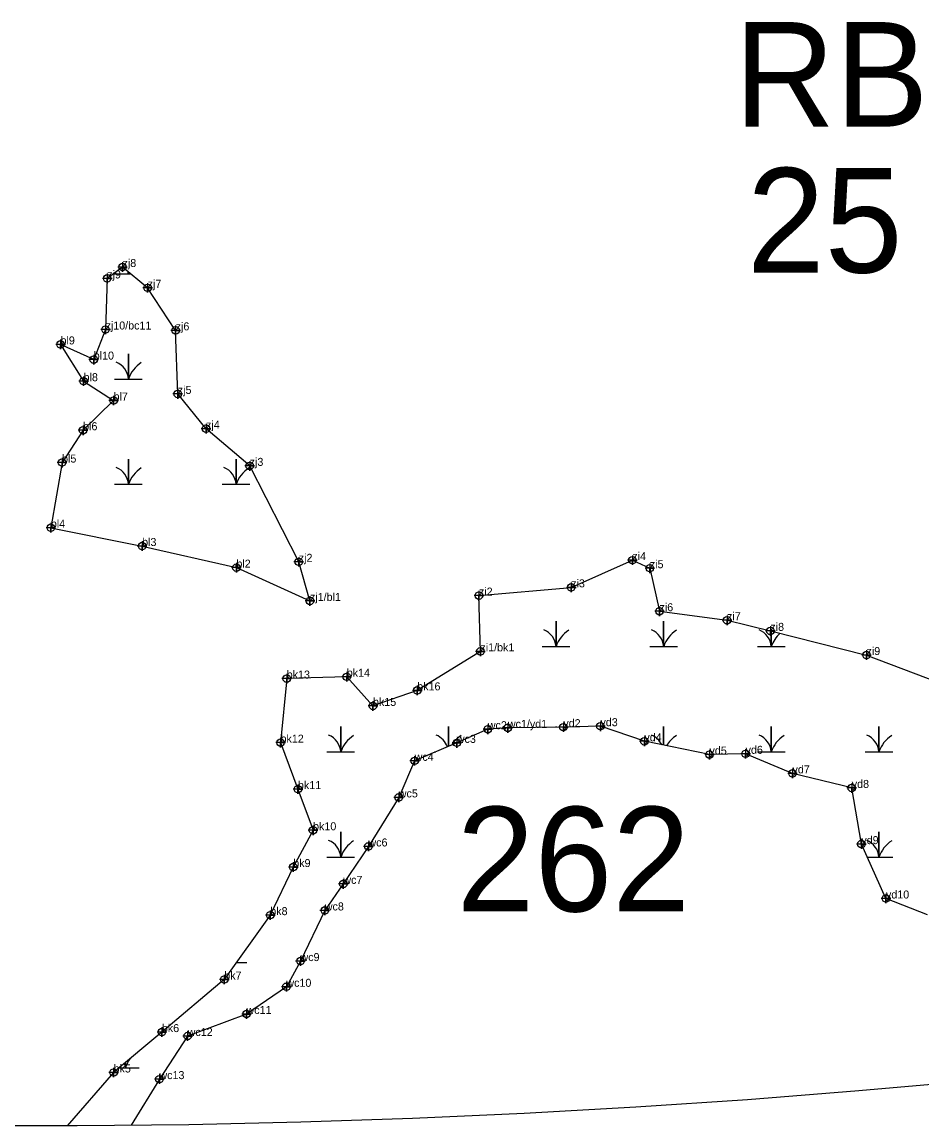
# Model space of a CAD drawing. Extents: x 2071991 to 2268989, y 436479 to 469629.
# Drawn here: x 2222499 to 2223061, y 436786 to 437475 of the extents above; entities that cross this region are included whole.
import ezdxf

# ---------------------------------------------------------------- set-up
doc = ezdxf.new("R2010")
doc.units = 0
for name, color, linetype in [('approx_PSA', 7, 'Continuous'), ('Default', 7, 'Continuous'), ('Exist Environmental Wetland Boundary', 7, 'Continuous'), ('Exist Environmental Wetland Boundary Cogo Comment', 7, 'Continuous'), ('Exist Environmental Wetland Boundary Cogo Point CELL', 7, 'Continuous'), ('Exist Hydro Swamp or Marsh', 7, 'Continuous')]:
    doc.layers.add(name, color=color, linetype=linetype)

msp = doc.modelspace()

# ---------------------------------------------------------------- linework, layer by layer
at = {"layer": 'approx_PSA'}
for p, q in [((2223091.14, 436813.8), (2223021.62, 436807.56)), ((2223021.62, 436807.56), (2222952.03, 436802.1)), ((2222952.03, 436802.1), (2222882.38, 436797.42)), ((2222812.68, 436793.52), (2222742.94, 436790.4)), ((2222882.38, 436797.42), (2222812.68, 436793.52)), ((2222603.39, 436786.5), (2222533.58, 436785.73)), ((2222673.17, 436788.06), (2222603.39, 436786.5)), ((2222742.94, 436790.4), (2222673.17, 436788.06)), ((2222533.58, 436785.73), (2222463.78, 436785.73))]:
    msp.add_line(p, q, dxfattribs=at)
at = {"layer": 'Exist Environmental Wetland Boundary'}
msp.add_lwpolyline([(2222678.94, 437113.66), (2222671.95, 437138.1), (2222641.29, 437198.03), (2222614.08, 437221.25), (2222596.41, 437242.97), (2222595.08, 437282.68), (2222577.59, 437309.25), (2222561.9, 437322.26), (2222552.35, 437315.12), (2222551.3, 437283.22), (2222543.94, 437264.43), (2222523.21, 437273.91), (2222537.6, 437250.93), (2222556.32, 437238.86), (2222537.3, 437220.3), (2222524.17, 437200.12), (2222517.16, 437159.39), (2222574.15, 437147.97), (2222633.01, 437134.45)], close=True, dxfattribs=at)
for points in [[(2222785.35, 437082.17), (2222784.41, 437117), (2222842.02, 437122.15), (2222880.21, 437139.14), (2222891.1, 437134.11), (2222897.14, 437107.23), (2222939.31, 437101.62), (2222966.35, 437094.96), (2223026.38, 437079.88), (2223078.67, 437060.04)], [(2222785.35, 437082.17), (2222745.89, 437057.79), (2222718.28, 437048.09), (2222701.91, 437066.28), (2222664.42, 437065.17), (2222660.56, 437025.14), (2222671.42, 436996.1), (2222680.87, 436970.41), (2222668.5, 436947.42), (2222654.15, 436917.39), (2222625.42, 436877.18), (2222586.46, 436844.34), (2222556.31, 436819.11), (2222527.37, 436785.73)], [(2223064.49, 436917.5), (2223038.53, 436927.79), (2223023.17, 436961.76), (2223017.18, 436996.86), (2222980.19, 437005.96), (2222950.9, 437018.17), (2222928.35, 437017.71), (2222887.69, 437025.99), (2222860.28, 437035.41), (2222837.11, 437034.81), (2222802.47, 437034.35), (2222789.96, 437033.53), (2222770.61, 437025), (2222744.29, 437013.79), (2222734.38, 436990.93), (2222715.43, 436960.31), (2222699.76, 436936.91), (2222688.19, 436920.33), (2222673, 436888.7), (2222664.19, 436872.65), (2222639.31, 436855.63), (2222602.57, 436841.89), (2222584.94, 436814.96), (2222567.3, 436786.1)]]:
    msp.add_lwpolyline(points, dxfattribs=at)
at = {"layer": 'Exist Environmental Wetland Boundary Cogo Point CELL'}
for points in [[(2222561.9, 437325.26), (2222561.9, 437319.26), (2222561.9, 437322.26), (2222564.9, 437322.26), (2222558.9, 437322.26)], [(2222552.35, 437318.12), (2222552.35, 437312.12), (2222552.35, 437315.12), (2222555.35, 437315.12), (2222549.35, 437315.12)], [(2222577.59, 437312.25), (2222577.59, 437306.25), (2222577.59, 437309.25), (2222580.59, 437309.25), (2222574.59, 437309.25)], [(2222551.3, 437286.22), (2222551.3, 437280.22), (2222551.3, 437283.22), (2222554.3, 437283.22), (2222548.3, 437283.22)], [(2222595.08, 437285.68), (2222595.08, 437279.68), (2222595.08, 437282.68), (2222598.08, 437282.68), (2222592.08, 437282.68)], [(2222523.21, 437276.91), (2222523.21, 437270.91), (2222523.21, 437273.91), (2222526.21, 437273.91), (2222520.21, 437273.91)], [(2222543.94, 437267.43), (2222543.94, 437261.43), (2222543.94, 437264.43), (2222546.94, 437264.43), (2222540.94, 437264.43)], [(2222537.6, 437253.93), (2222537.6, 437247.93), (2222537.6, 437250.93), (2222540.6, 437250.93), (2222534.6, 437250.93)], [(2222556.32, 437241.86), (2222556.32, 437235.86), (2222556.32, 437238.86), (2222559.32, 437238.86), (2222553.32, 437238.86)], [(2222596.41, 437245.97), (2222596.41, 437239.97), (2222596.41, 437242.97), (2222599.41, 437242.97), (2222593.41, 437242.97)], [(2222537.3, 437223.3), (2222537.3, 437217.3), (2222537.3, 437220.3), (2222540.3, 437220.3), (2222534.3, 437220.3)], [(2222614.08, 437224.25), (2222614.08, 437218.25), (2222614.08, 437221.25), (2222617.08, 437221.25), (2222611.08, 437221.25)], [(2222524.17, 437203.12), (2222524.17, 437197.12), (2222524.17, 437200.12), (2222527.17, 437200.12), (2222521.17, 437200.12)], [(2222641.29, 437201.03), (2222641.29, 437195.03), (2222641.29, 437198.03), (2222644.29, 437198.03), (2222638.29, 437198.03)], [(2222517.16, 437162.39), (2222517.16, 437156.39), (2222517.16, 437159.39), (2222520.16, 437159.39), (2222514.16, 437159.39)], [(2222574.15, 437150.97), (2222574.15, 437144.97), (2222574.15, 437147.97), (2222577.15, 437147.97), (2222571.15, 437147.97)], [(2222671.95, 437141.1), (2222671.95, 437135.1), (2222671.95, 437138.1), (2222674.95, 437138.1), (2222668.95, 437138.1)], [(2222880.21, 437142.14), (2222880.21, 437136.14), (2222880.21, 437139.14), (2222883.21, 437139.14), (2222877.21, 437139.14)], [(2222633.01, 437137.45), (2222633.01, 437131.45), (2222633.01, 437134.45), (2222636.01, 437134.45), (2222630.01, 437134.45)], [(2222891.1, 437137.11), (2222891.1, 437131.11), (2222891.1, 437134.11), (2222894.1, 437134.11), (2222888.1, 437134.11)], [(2222842.02, 437125.15), (2222842.02, 437119.15), (2222842.02, 437122.15), (2222845.02, 437122.15), (2222839.02, 437122.15)], [(2222784.41, 437120), (2222784.41, 437114), (2222784.41, 437117), (2222787.41, 437117), (2222781.41, 437117)], [(2222678.94, 437116.66), (2222678.94, 437110.66), (2222678.94, 437113.66), (2222681.94, 437113.66), (2222675.94, 437113.66)], [(2222897.14, 437110.23), (2222897.14, 437104.23), (2222897.14, 437107.23), (2222900.14, 437107.23), (2222894.14, 437107.23)], [(2222939.31, 437104.62), (2222939.31, 437098.62), (2222939.31, 437101.62), (2222942.31, 437101.62), (2222936.31, 437101.62)], [(2222966.35, 437097.96), (2222966.35, 437091.96), (2222966.35, 437094.96), (2222969.35, 437094.96), (2222963.35, 437094.96)], [(2222785.35, 437085.17), (2222785.35, 437079.17), (2222785.35, 437082.17), (2222788.35, 437082.17), (2222782.35, 437082.17)], [(2223026.38, 437082.88), (2223026.38, 437076.88), (2223026.38, 437079.88), (2223029.38, 437079.88), (2223023.38, 437079.88)], [(2222701.91, 437069.28), (2222701.91, 437063.28), (2222701.91, 437066.28), (2222704.91, 437066.28), (2222698.91, 437066.28)], [(2222664.42, 437068.17), (2222664.42, 437062.17), (2222664.42, 437065.17), (2222667.42, 437065.17), (2222661.42, 437065.17)], [(2222745.89, 437060.79), (2222745.89, 437054.79), (2222745.89, 437057.79), (2222748.89, 437057.79), (2222742.89, 437057.79)], [(2222718.28, 437051.09), (2222718.28, 437045.09), (2222718.28, 437048.09), (2222721.28, 437048.09), (2222715.28, 437048.09)], [(2222789.96, 437036.53), (2222789.96, 437030.53), (2222789.96, 437033.53), (2222792.96, 437033.53), (2222786.96, 437033.53)], [(2222802.47, 437037.35), (2222802.47, 437031.35), (2222802.47, 437034.35), (2222805.47, 437034.35), (2222799.47, 437034.35)], [(2222837.11, 437037.81), (2222837.11, 437031.81), (2222837.11, 437034.81), (2222840.11, 437034.81), (2222834.11, 437034.81)], [(2222860.28, 437038.41), (2222860.28, 437032.41), (2222860.28, 437035.41), (2222863.28, 437035.41), (2222857.28, 437035.41)], [(2222660.56, 437028.14), (2222660.56, 437022.14), (2222660.56, 437025.14), (2222663.56, 437025.14), (2222657.56, 437025.14)], [(2222770.61, 437028), (2222770.61, 437022), (2222770.61, 437025), (2222773.61, 437025), (2222767.61, 437025)], [(2222887.69, 437028.99), (2222887.69, 437022.99), (2222887.69, 437025.99), (2222890.69, 437025.99), (2222884.69, 437025.99)], [(2222928.35, 437020.71), (2222928.35, 437014.71), (2222928.35, 437017.71), (2222931.35, 437017.71), (2222925.35, 437017.71)], [(2222950.9, 437021.17), (2222950.9, 437015.17), (2222950.9, 437018.17), (2222953.9, 437018.17), (2222947.9, 437018.17)], [(2222744.29, 437016.79), (2222744.29, 437010.79), (2222744.29, 437013.79), (2222747.29, 437013.79), (2222741.29, 437013.79)], [(2222980.19, 437008.96), (2222980.19, 437002.96), (2222980.19, 437005.96), (2222983.19, 437005.96), (2222977.19, 437005.96)], [(2223017.18, 436999.86), (2223017.18, 436993.86), (2223017.18, 436996.86), (2223020.18, 436996.86), (2223014.18, 436996.86)], [(2222671.42, 436999.1), (2222671.42, 436993.1), (2222671.42, 436996.1), (2222674.42, 436996.1), (2222668.42, 436996.1)], [(2222734.38, 436993.93), (2222734.38, 436987.93), (2222734.38, 436990.93), (2222737.38, 436990.93), (2222731.38, 436990.93)], [(2222680.87, 436973.41), (2222680.87, 436967.41), (2222680.87, 436970.41), (2222683.87, 436970.41), (2222677.87, 436970.41)], [(2222715.43, 436963.31), (2222715.43, 436957.31), (2222715.43, 436960.31), (2222718.43, 436960.31), (2222712.43, 436960.31)], [(2223023.17, 436964.76), (2223023.17, 436958.76), (2223023.17, 436961.76), (2223026.17, 436961.76), (2223020.17, 436961.76)], [(2222668.5, 436950.42), (2222668.5, 436944.42), (2222668.5, 436947.42), (2222671.5, 436947.42), (2222665.5, 436947.42)], [(2222699.76, 436939.91), (2222699.76, 436933.91), (2222699.76, 436936.91), (2222702.76, 436936.91), (2222696.76, 436936.91)], [(2223038.53, 436930.79), (2223038.53, 436924.79), (2223038.53, 436927.79), (2223041.53, 436927.79), (2223035.53, 436927.79)], [(2222654.15, 436920.39), (2222654.15, 436914.39), (2222654.15, 436917.39), (2222657.15, 436917.39), (2222651.15, 436917.39)], [(2222688.19, 436923.33), (2222688.19, 436917.33), (2222688.19, 436920.33), (2222691.19, 436920.33), (2222685.19, 436920.33)], [(2222673, 436891.7), (2222673, 436885.7), (2222673, 436888.7), (2222676, 436888.7), (2222670, 436888.7)], [(2222625.42, 436880.18), (2222625.42, 436874.18), (2222625.42, 436877.18), (2222628.42, 436877.18), (2222622.42, 436877.18)], [(2222664.19, 436875.65), (2222664.19, 436869.65), (2222664.19, 436872.65), (2222667.19, 436872.65), (2222661.19, 436872.65)], [(2222639.31, 436858.63), (2222639.31, 436852.63), (2222639.31, 436855.63), (2222642.31, 436855.63), (2222636.31, 436855.63)], [(2222586.46, 436847.34), (2222586.46, 436841.34), (2222586.46, 436844.34), (2222589.46, 436844.34), (2222583.46, 436844.34)], [(2222602.57, 436844.89), (2222602.57, 436838.89), (2222602.57, 436841.89), (2222605.57, 436841.89), (2222599.57, 436841.89)], [(2222556.31, 436822.11), (2222556.31, 436816.11), (2222556.31, 436819.11), (2222559.31, 436819.11), (2222553.31, 436819.11)], [(2222584.94, 436817.96), (2222584.94, 436811.96), (2222584.94, 436814.96), (2222587.94, 436814.96), (2222581.94, 436814.96)]]:
    msp.add_lwpolyline(points, dxfattribs=at)
for centre in [(2222561.9, 437322.26), (2222552.35, 437315.12), (2222577.59, 437309.25), (2222551.3, 437283.22), (2222595.08, 437282.68), (2222523.21, 437273.91), (2222543.94, 437264.43), (2222537.6, 437250.93), (2222556.32, 437238.86), (2222596.41, 437242.97), (2222537.3, 437220.3), (2222614.08, 437221.25), (2222524.17, 437200.12), (2222641.29, 437198.03), (2222517.16, 437159.39), (2222574.15, 437147.97), (2222671.95, 437138.1), (2222880.21, 437139.14), (2222633.01, 437134.45), (2222891.1, 437134.11), (2222842.02, 437122.15), (2222784.41, 437117), (2222678.94, 437113.66), (2222897.14, 437107.23), (2222939.31, 437101.62), (2222966.35, 437094.96), (2222785.35, 437082.17), (2223026.38, 437079.88), (2222701.91, 437066.28), (2222664.42, 437065.17), (2222745.89, 437057.79), (2222718.28, 437048.09), (2222789.96, 437033.53), (2222802.47, 437034.35), (2222837.11, 437034.81), (2222860.28, 437035.41), (2222660.56, 437025.14), (2222770.61, 437025), (2222887.69, 437025.99), (2222950.9, 437018.17), (2222744.29, 437013.79), (2222928.35, 437017.71), (2222980.19, 437005.96), (2222671.42, 436996.1), (2222734.38, 436990.93), (2223017.18, 436996.86), (2222680.87, 436970.41), (2222715.43, 436960.31), (2223023.17, 436961.76), (2222668.5, 436947.42), (2222699.76, 436936.91), (2223038.53, 436927.79), (2222654.15, 436917.39), (2222688.19, 436920.33), (2222673, 436888.7), (2222625.42, 436877.18), (2222664.19, 436872.65), (2222639.31, 436855.63), (2222586.46, 436844.34), (2222602.57, 436841.89), (2222556.31, 436819.11), (2222584.94, 436814.96)]:
    msp.add_circle(centre, 2.34, dxfattribs=at)
at = {"layer": 'Exist Hydro Swamp or Marsh'}
for p, q in [((2222756.74, 437019.4), (2222757.45, 437019.4)), ((2222633.03, 436887.83), (2222639.53, 436887.83))]:
    msp.add_line(p, q, dxfattribs=at)
for points in [[(2222556.99, 437318.08), (2222565.59, 437318.08), (2222565.59, 437319.2)], [(2222565.59, 437319.2), (2222565.59, 437318.08), (2222566.95, 437318.08)], [(2222556.99, 437252.29), (2222565.59, 437252.29), (2222565.59, 437268.08), (2222565.59, 437252.29), (2222574.19, 437252.29)], [(2222556.99, 437186.51), (2222565.59, 437186.51), (2222565.59, 437202.29), (2222565.59, 437186.51), (2222574.19, 437186.51)], [(2222624.19, 437186.51), (2222632.79, 437186.51), (2222632.79, 437202.29), (2222632.79, 437186.51), (2222641.4, 437186.51)], [(2222632.79, 437134.49), (2222632.79, 437136.51), (2222632.79, 437134.49)], [(2222823.94, 437085.18), (2222832.54, 437085.18), (2222832.54, 437100.96), (2222832.54, 437085.18), (2222841.14, 437085.18)], [(2222891.14, 437085.18), (2222899.74, 437085.18), (2222899.74, 437100.96), (2222899.74, 437085.18), (2222908.35, 437085.18)], [(2222958.35, 437085.18), (2222966.95, 437085.18), (2222966.95, 437094.81)], [(2222966.95, 437094.81), (2222966.95, 437085.18), (2222975.55, 437085.18)], [(2222689.53, 437019.4), (2222698.13, 437019.4), (2222698.13, 437035.18), (2222698.13, 437019.4), (2222706.74, 437019.4)], [(2222765.34, 437022.76), (2222765.34, 437035.18), (2222765.34, 437022.76)], [(2222832.54, 437034.75), (2222832.54, 437035.18), (2222832.54, 437034.75)], [(2222899.74, 437023.53), (2222899.74, 437035.18), (2222899.74, 437023.53)], [(2222958.35, 437019.4), (2222966.95, 437019.4), (2222966.95, 437035.18), (2222966.95, 437019.4), (2222975.55, 437019.4)], [(2223025.55, 437019.4), (2223034.15, 437019.4), (2223034.15, 437035.18), (2223034.15, 437019.4), (2223042.75, 437019.4)], [(2222689.53, 436953.62), (2222698.13, 436953.62), (2222698.13, 436969.4), (2222698.13, 436953.62), (2222706.74, 436953.62)], [(2223026.85, 436953.62), (2223034.15, 436953.62), (2223034.15, 436969.4), (2223034.15, 436953.62), (2223042.75, 436953.62)], [(2222559.83, 436822.05), (2222563.73, 436822.05), (2222563.73, 436825.32)], [(2222563.73, 436825.32), (2222563.73, 436822.05), (2222572.33, 436822.05)]]:
    msp.add_lwpolyline(points, dxfattribs=at)
for centre, radius, start, end in [((2222553.32, 437317.19), 12.3, 4.14034, 10.03464), ((2222583.83, 437312.01), 19.22, 158.87528, 161.62219), ((2222553.32, 437251.41), 12.3, 4.14034, 67.53497), ((2222583.83, 437246.23), 19.22, 122.12745, 161.62219), ((2222553.32, 437185.63), 12.3, 4.14034, 67.53497), ((2222583.83, 437180.45), 19.22, 122.12745, 161.62219), ((2222620.53, 437185.63), 12.3, 4.14034, 67.53497), ((2222651.04, 437180.45), 19.22, 122.12745, 161.62219), ((2222651.04, 437114.67), 19.22, 122.12745, 122.25053), ((2222820.27, 437084.29), 12.3, 4.14034, 67.53497), ((2222850.78, 437079.12), 19.22, 122.12745, 161.62219), ((2222887.48, 437084.29), 12.3, 4.14034, 67.53497), ((2222917.99, 437079.12), 19.22, 122.12745, 161.62219), ((2222954.68, 437084.29), 12.3, 4.14034, 67.53497), ((2222985.19, 437079.12), 19.22, 131.78708, 161.62219), ((2222685.87, 437018.51), 12.3, 4.14034, 67.53497), ((2222716.38, 437013.34), 19.22, 122.12745, 161.62219), ((2222753.07, 437018.51), 12.3, 18.88249, 67.53497), ((2222783.58, 437013.34), 19.22, 122.12745, 147.70721), ((2222887.48, 437018.51), 12.3, 25.32564, 67.53497), ((2222917.99, 437013.34), 19.22, 122.12745, 149.18698), ((2222954.68, 437018.51), 12.3, 4.14034, 67.53497), ((2222985.19, 437013.34), 19.22, 122.12745, 161.62219), ((2223021.88, 437018.51), 12.3, 4.14034, 67.53497), ((2223052.39, 437013.34), 19.22, 122.12745, 161.62219), ((2222685.87, 436952.73), 12.3, 4.14034, 67.53497), ((2222716.38, 436947.55), 19.22, 122.12745, 161.62219), ((2223021.88, 436952.73), 12.3, 4.14034, 67.53497), ((2223052.39, 436947.55), 19.22, 122.12745, 161.62219), ((2222581.97, 436815.99), 19.22, 141.13887, 161.62219), ((2222551.46, 436821.17), 12.3, 4.14034, 17.50735)]:
    msp.add_arc(centre, radius, start, end, dxfattribs=at)

# ---------------------------------------------------------------- texts
at = {"layer": 'Default'}
for s, p in [('RB', (2222943.67, 437409.92)), ('25', (2222951.72, 437318.77)), ('262', (2222770.51, 436919.7))]:
    msp.add_text(s, height=65.34, dxfattribs=at).set_placement(p)
at = {"layer": 'Exist Environmental Wetland Boundary Cogo Comment'}
for s, p in [('zj8', (2222561.9, 437322.26)), ('zj9', (2222552.35, 437315.12)), ('zj7', (2222577.59, 437309.25)), ('zj10/bc11', (2222551.3, 437283.22)), ('zj6', (2222595.08, 437282.68)), ('bl9', (2222523.21, 437273.91)), ('bl10', (2222543.94, 437264.43)), ('bl8', (2222537.6, 437250.93)), ('zj5', (2222596.41, 437242.97)), ('bl7', (2222556.32, 437238.86)), ('bl6', (2222537.3, 437220.3)), ('zj4', (2222614.08, 437221.25)), ('bl5', (2222524.17, 437200.12)), ('zj3', (2222641.29, 437198.03)), ('bl4', (2222517.16, 437159.39)), ('bl3', (2222574.15, 437147.97)), ('bl2', (2222633.01, 437134.45)), ('zj2', (2222671.95, 437138.1)), ('zi4', (2222880.21, 437139.14)), ('zi5', (2222891.1, 437134.11)), ('zi3', (2222842.02, 437122.15)), ('zj1/bl1', (2222678.94, 437113.66)), ('zi2', (2222784.41, 437117)), ('zi6', (2222897.14, 437107.23)), ('zi7', (2222939.31, 437101.62)), ('zi8', (2222966.35, 437094.96)), ('zi1/bk1', (2222785.35, 437082.17)), ('zi9', (2223026.38, 437079.88)), ('bk13', (2222664.42, 437065.17)), ('bk14', (2222701.91, 437066.28)), ('bk16', (2222745.89, 437057.79)), ('bk15', (2222718.28, 437048.09)), ('wc2', (2222789.96, 437033.53)), ('wc1/yd1', (2222802.47, 437034.35)), ('yd2', (2222837.11, 437034.81)), ('yd3', (2222860.28, 437035.41)), ('bk12', (2222660.56, 437025.14)), ('wc3', (2222770.61, 437025)), ('yd4', (2222887.69, 437025.99)), ('yd5', (2222928.35, 437017.71)), ('yd6', (2222950.9, 437018.17)), ('wc4', (2222744.29, 437013.79)), ('yd7', (2222980.19, 437005.96)), ('bk11', (2222671.42, 436996.1)), ('yd8', (2223017.18, 436996.86)), ('wc5', (2222734.38, 436990.93)), ('bk10', (2222680.87, 436970.41)), ('wc6', (2222715.43, 436960.31)), ('yd9', (2223023.17, 436961.76)), ('bk9', (2222668.5, 436947.42)), ('wc7', (2222699.76, 436936.91)), ('yd10', (2223038.53, 436927.79)), ('wc8', (2222688.19, 436920.33)), ('bk8', (2222654.15, 436917.39)), ('wc9', (2222673, 436888.7)), ('bk7', (2222625.42, 436877.18)), ('wc10', (2222664.19, 436872.65)), ('wc11', (2222639.31, 436855.63)), ('bk6', (2222586.46, 436844.34)), ('wc12', (2222602.57, 436841.89)), ('bk5', (2222556.31, 436819.11)), ('wc13', (2222584.94, 436814.96))]:
    msp.add_text(s, height=5, dxfattribs=at).set_placement(p)

doc.saveas('drawing.dxf')
